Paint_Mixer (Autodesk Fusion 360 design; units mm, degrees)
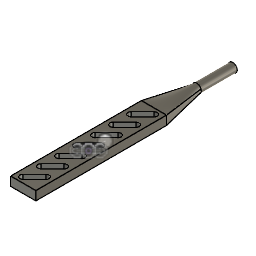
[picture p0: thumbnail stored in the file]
sketch "Sketch1" plane through (0, 0, 0) normal (0, 0, 1) x axis (1, 0, 0)
  line L1 (-14, 72.5) -> (14, 72.5)
  line L2 (-14, -72.5) -> (-14, 72.5)
  line L3 (14, -72.5) -> (-14, -72.5)
  line L4 (14, 72.5) -> (14, -72.5)
  line L5 (-14, -72.5) -> (14, 72.5)
  line L6 (14, -72.5) -> (-14, 72.5)
  point P6 (0, 0)
  point P1 (0, 0)
  point P2 (14, 72.5)
  point P3 (-14, 72.5)
  point P4 (-14, -72.5)
  horizontal L1
  perpendicular L1 L2
  parallel L1 L3
  parallel L2 L4
  coincident L5 P6
  coincident L6 P6
  coincident P1 P6
  dimension "d1" distance P2 P3 = 28
  dimension "d2" distance P3 P4 = 145
extrude "Extrude1" new body sketch "Sketch1" profile of L1 L2 L3 L4 distance 5
sketch "Sketch2" plane through (0, 0, 0) normal (0, 0, 1) x axis (1, 0, 0)
  line L1 (8.8388, 3.8891) -> (-3.8891, -8.8388)
  line L2 (-8.8388, -3.8891) -> (3.8891, 8.8388)
  line L3 (6.364, 6.364) -> (-6.364, -6.364)
  line L4 (0, 18.3576) -> (0, 0)
  arc A1 centre (6.364, 6.364) radius 3.5 clockwise from (3.8891, 8.8388) to (8.8388, 3.8891)
  arc A2 centre (-6.364, -6.364) radius 3.5 clockwise from (-3.8891, -8.8388) to (-8.8388, -3.8891)
  point P1 (0, 0)
  point P8 (0, 0)
  point P9 (0, 0)
  point P6 (-6.364, -6.364)
  point P7 (6.364, 6.364)
  tangent L1 A1
  tangent A1 L2
  parallel L1 L2
  tangent L2 A2
  tangent L1 A2
  coincident P1 P8
  midpoint L3 P8
  coincident P8 P9
  vertical L4
  dimension "d5" distance P6 P7 = 18
  dimension "d6" radius A1 = 3.5
  dimension "d7" angle L3 L4 = 45
extrude "Extrude2" cut sketch "Sketch2" profile of L1 A1 L2 A2 distance 10
work_plane "WorkPlane1" AlongDistance 120
sketch "Sketch3" plane through (0, 120, 0) normal (0, 1, 0) x axis (1, 0, 0)
  circle C1 centre (0, 0) radius 5
  point P1 (0, 0)
  point P2 (0, 0)
  coincident P1 P2
  dimension "d11" diameter C1 = 10
extrude "Extrude3" new body sketch "Sketch3" along normal blind 40
loft "Loft1"
rectangular_pattern "R-Pattern1" uSpaceDistance 20 vSpaceDistance 0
